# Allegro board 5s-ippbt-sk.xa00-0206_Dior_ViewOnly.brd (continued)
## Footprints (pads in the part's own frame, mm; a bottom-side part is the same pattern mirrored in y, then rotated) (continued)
MX_C0402_SMALL
  rect 0.457x0.508 smd: 1(0.419,0) 2(-0.419,0)
MX_C0402_SMALL_T01
  rect 0.457x0.508 smd: 1(0.419,0) 2(-0.419,0)
MX_C0603_SMALL
  rect 0.559x0.889 smd: 1(-0.67,0) 2(0.67,0)
MX_C0603_SMALL_T01
  rect 0.559x0.889 smd: 1(-0.67,0) 2(0.67,0)
MX_C0603_SMALL_T02
  rect 0.559x0.991 smd: 1(-0.67,0) 2(0.67,0)
MX_C0805_SMALL
  rect 0.813x1.397 smd: 1(0.9,0) 2(-0.9,0)
MX_C0805_SMALL_T02
  rect 0.711x1.397 smd: 1(-0.864,0) 2(0.864,0)
MX_C1206_H75
  rect 1.041x1.6 smd: 1(1.52,0) 2(-1.52,0)
MX_C3528
  rect 1.905x2.21 smd: 1(1.816,0) 2(-1.816,0)
MX_C7343D_H79
  rect 2.032x2.616 smd: 1(3.265,0) 2(-3.265,0)
MX_CESMD_260X260_H248
  rect 3.505x1.016 smd: 1(2.655,0) 2(-2.655,0)
MX_CHOKE_4P_79X47_FUKUI
  rect 0.889x0.356 smd: 1(-0.85,-0.425) 2(0.85,-0.425) 3(0.85,0.425) 4(-0.85,0.425)
MX_DC_PWR_JACK_6P_LF3
  oval 1.626x3.023 hole 0.61: 1(-1.12,7.65) 2_1(-3.9,5.3) 2_3(-3.9,0) 2_4(3.9,0)
  oval 1.372x2.769 hole 0.61: 2_2(3.9,5.3)
  oval 1.803x2.21 hole 0.787: 3(2.3,8)
MX_DDR3_DIMM_204P_24_4HD_AR
  round 1.6 hole 1.6 unplated: (-33.4,0)
  round 1.092 hole 1.092 unplated: (33.4,0)
  rect 0.356x2.007 smd: 1(-31.65,-4.1) 2(-31.35,4.1) 3(-31.05,-4.1) 4(-30.75,4.1) 5(-30.45,-4.1) 6(-30.15,4.1) 7(-29.85,-4.1) 8(-29.55,4.1) 9(-29.25,-4.1) 10(-28.95,4.1) 11(-28.65,-4.1) 12(-28.35,4.1) 13(-28.05,-4.1) 14(-27.75,4.1) 15(-27.45,-4.1) 16(-27.15,4.1) 17(-26.85,-4.1) 18(-26.55,4.1) 19(-26.25,-4.1) 20(-25.95,4.1) 21(-25.65,-4.1) 22(-25.35,4.1) 23(-25.05,-4.1) 24(-24.75,4.1) 25(-24.45,-4.1) 26(-24.15,4.1) 27(-23.85,-4.1) 28(-23.55,4.1) 29(-23.25,-4.1) 30(-22.95,4.1) 31(-22.65,-4.1) 32(-22.35,4.1) 33(-22.05,-4.1) 34(-21.75,4.1) 35(-21.45,-4.1) 36(-21.15,4.1) 37(-20.85,-4.1) 38(-20.55,4.1) 39(-20.25,-4.1) 40(-19.95,4.1) 41(-19.65,-4.1) 42(-19.35,4.1) 43(-19.05,-4.1) 44(-18.75,4.1) 45(-18.45,-4.1) 46(-18.15,4.1) 47(-17.85,-4.1) 48(-17.55,4.1) 49(-17.25,-4.1) 50(-16.95,4.1) 51(-16.65,-4.1) 52(-16.35,4.1) 53(-16.05,-4.1) 54(-15.75,4.1) 55(-15.45,-4.1) 56(-15.15,4.1) 57(-14.85,-4.1) 58(-14.55,4.1) 59(-14.25,-4.1) 60(-13.95,4.1) 61(-13.65,-4.1) 62(-13.35,4.1) 63(-13.05,-4.1) 64(-12.75,4.1) 65(-12.45,-4.1) 66(-12.15,4.1) 67(-11.85,-4.1) 68(-11.55,4.1) 69(-11.25,-4.1) 70(-10.95,4.1) 71(-10.65,-4.1) 72(-10.35,4.1) 73(-7.65,-4.1) 74(-7.35,4.1) 75(-7.05,-4.1) 76(-6.75,4.1) 77(-6.45,-4.1) 78(-6.15,4.1) 79(-5.85,-4.1) 80(-5.55,4.1) 81(-5.25,-4.1) 82(-4.95,4.1) 83(-4.65,-4.1) 84(-4.35,4.1) 85(-4.05,-4.1) 86(-3.75,4.1) 87(-3.45,-4.1) 88(-3.15,4.1) 89(-2.85,-4.1) 90(-2.55,4.1) 91(-2.25,-4.1) 92(-1.95,4.1) 93(-1.65,-4.1) 94(-1.35,4.1) 95(-1.05,-4.1) 96(-0.75,4.1) 97(-0.45,-4.1) 98(-0.15,4.1) 99(0.15,-4.1) 100(0.45,4.1) 101(0.75,-4.1) 102(1.05,4.1) 103(1.35,-4.1) 104(1.65,4.1) 105(1.95,-4.1) 106(2.25,4.1) 107(2.55,-4.1) 108(2.85,4.1) 109(3.15,-4.1) 110(3.45,4.1) 111(3.75,-4.1) 112(4.05,4.1) 113(4.35,-4.1) 114(4.65,4.1) 115(4.95,-4.1) 116(5.25,4.1) 117(5.55,-4.1) 118(5.85,4.1) 119(6.15,-4.1) 120(6.45,4.1) 121(6.75,-4.1) 122(7.05,4.1) 123(7.35,-4.1) 124(7.65,4.1) 125(7.95,-4.1) 126(8.25,4.1) 127(8.55,-4.1) 128(8.85,4.1) 129(9.15,-4.1) 130(9.45,4.1) 131(9.75,-4.1) 132(10.05,4.1) 133(10.35,-4.1) 134(10.65,4.1) 135(10.95,-4.1) 136(11.25,4.1) 137(11.55,-4.1) 138(11.85,4.1) 139(12.15,-4.1) 140(12.45,4.1) 141(12.75,-4.1) 142(13.05,4.1) 143(13.35,-4.1) 144(13.65,4.1) 145(13.95,-4.1) 146(14.25,4.1) 147(14.55,-4.1) 148(14.85,4.1) 149(15.15,-4.1) 150(15.45,4.1) 151(15.75,-4.1) 152(16.05,4.1) 153(16.35,-4.1) 154(16.65,4.1) 155(16.95,-4.1) 156(17.25,4.1) 157(17.55,-4.1) 158(17.85,4.1) 159(18.15,-4.1) 160(18.45,4.1) 161(18.75,-4.1) 162(19.05,4.1) 163(19.35,-4.1) 164(19.65,4.1) 165(19.95,-4.1) 166(20.25,4.1) 167(20.55,-4.1) 168(20.85,4.1) 169(21.15,-4.1) 170(21.45,4.1) 171(21.75,-4.1) 172(22.05,4.1) 173(22.35,-4.1) 174(22.65,4.1) 175(22.95,-4.1) 176(23.25,4.1) 177(23.55,-4.1) 178(23.85,4.1) 179(24.15,-4.1) 180(24.45,4.1) 181(24.75,-4.1) 182(25.05,4.1) 183(25.35,-4.1) 184(25.65,4.1) 185(25.95,-4.1) 186(26.25,4.1) 187(26.55,-4.1) 188(26.85,4.1) 189(27.15,-4.1) 190(27.45,4.1) 191(27.75,-4.1) 192(28.05,4.1) 193(28.35,-4.1) 194(28.65,4.1) 195(28.95,-4.1) 196(29.25,4.1) 197(29.55,-4.1) 198(29.85,4.1) 199(30.15,-4.1) 200(30.45,4.1) 201(30.75,-4.1) 202(31.05,4.1) 203(31.35,-4.1) 204(31.65,4.1)
  rect 4.699x6.807 smd: 207(-37.35,11.3) 208(37.35,11.3)
MX_DFN_6P_26_79X79_2PAD_IR
  rect 0.381x0.457 smd: 1(-0.65,-0.925) 2(0,-0.925) 3(0.65,-0.925) 4(0.65,0.925) 5(0,0.925) 6(-0.65,0.925)
  rect 1.041x0.965 smd: 7(-0.28,0.002)
  rect 0.229x0.787 smd: 8(0.735,0.002)
MX_DFN_10P_20_S118_P_RI_2V
  rect 0.279x0.61 smd: 1(-1,-1.35) 2(-0.5,-1.35) 3(0,-1.35) 4(0.5,-1.35) 5(1,-1.35) 6(1,1.35) 7(0.5,1.35) 8(0,1.35) 9(-0.5,1.35) 10(-1,1.35)
  rect 2.642x1.676 smd: 11(0,0)
  round 0.61 hole 0.305: 12(-1,0) 13(1,0)
MX_ESD_10P_20_98X39_NXP
  rect 0.295x0.483 smd: 1(-1,-0.363) 2(-0.5,-0.363) 3(0,-0.363) 4(0.5,-0.363) 5(1,-0.363) 6(1,0.363) 7(0.5,0.363) 8(0,0.363) 9(-0.5,0.363) 10(-1,0.363)
MX_FPC_10P_20_2H_RA_AC_H79
  rect 0.292x1.092 smd: 1(-2.25,1.95) 2(-1.75,1.95) 3(-1.25,1.95) 4(-0.75,1.95) 5(-0.25,1.95) 6(0.25,1.95) 7(0.75,1.95) 8(1.25,1.95) 9(1.75,1.95) 10(2.25,1.95)
  custom 0.6x0.6 smd: 11(-4.35,0) 12(4.35,0)
MX_FPC_12P_39_4HD
  rect 0.61x1.499 smd: 1(-2.75,-1.5) 2(-2.25,1.5) 3(-1.75,-1.5) 4(-1.25,1.5) 5(-0.75,-1.5) 6(-0.25,1.5) 7(0.25,-1.5) 8(0.75,1.5) 9(1.25,-1.5) 10(1.75,1.5) 11(2.25,-1.5) 12(2.75,1.5)
  rect 0.787x1.499 smd: 13(-3.75,-1.5) 14(-3.75,1.5) 15(3.75,-1.5) 16(3.75,1.5)
MX_HD_1X3P_100_LF3
  rect 1.575x1.575 hole 1.168: 1(-2.54,0)
  round 1.575 hole 1.168: 2(0,0) 3(2.54,0)
MX_HD_2X2P_50_JV
  rect 0.787x2.388 smd: 1(-0.635,-2.05) 2(-0.635,2.05) 3(0.635,-2.05) 4(0.635,2.05)
MX_HD_2X5P_79_K4_PINREX
  rect 0.838x2.591 smd: 1(-4,-2.05) 2(-4,2.05) 3(-2,-2.05) 5(0,-2.05) 6(0,2.05) 7(2,-2.05) 8(2,2.05) 9(4,-2.05) 10(4,2.05)
MX_HDMI_CON_19P_6H_SING_LF3
  round 1.702 hole 1.702 unplated: (-1.75,6.625)
  round 1.753 hole 1.753 unplated: (1.75,-6.625)
  round 0.94 hole 0.584: 1(0.75,-4.725) 2(-0.25,-4.147) 3(0.75,-3.57) 4(-0.25,-2.992) 5(0.75,-2.415) 6(-0.25,-1.837) 7(0.75,-1.26) 8(-0.25,-0.682) 9(0.75,-0.105) 10(-0.25,0.473) 11(0.75,1.05) 12(-0.25,1.628) 13(0.75,2.205) 14(-0.25,2.783) 15(0.75,3.36) 16(-0.25,3.938) 17(0.75,4.515) 18(-0.25,5.093) 19(0.75,5.67)
  oval 1.676x3.251 hole 0.66: 22(-3,-5.475) 23(-3,3.525) 24(3.5,-2.875) 25(3.5,6.625)
MX_HOLE_C59D59N
  round 1.499 hole 1.499 unplated: (0,0)
MX_HOLE_C118D118N
  round 2.997 hole 2.997 unplated: (0,0)
MX_HOLEC315D157N_M2P2V8
  round 3.988 hole 3.988 unplated: (0,0)
  round 0.61 hole 0.305: 2(0,3.004) 3(2.124,2.124) 4(3.004,0) 5(2.124,-2.124) 6(0,-3.004) 7(-2.124,-2.124) 8(-3.004,0) 9(-2.124,2.124)
MX_INDUCTOR_2P_287X260
  rect 2.845x2.997 smd: 1(-3.025,0) 2(3.025,0)
MX_L0603_SMALL
  rect 0.559x0.889 smd: 1(-0.67,0) 2(0.67,0)
MX_L0603_SMALL_T02
  rect 0.559x0.991 smd: 1(-0.67,0) 2(0.67,0)
MX_L0805_SMALL_T02_H43
  rect 0.711x1.397 smd: 1(-0.864,0) 2(0.864,0)
MX_MINI_PCI_67P_4HD_COLAY
  round 1.092 hole 1.092 unplated: (-10,0)
  round 1.6 hole 1.6 unplated: (10,0)
  rect 0.305x1.549 smd: 1(-9.25,5.275) 2(-9,-2.275) 3(-8.75,5.275) 4(-8.5,-2.275) 5(-8.25,5.275) 6(-8,-2.275) 7(-7.75,5.275) 16(-5.5,-2.275) 17(-5.25,5.275) 18(-5,-2.275) 19(-4.75,5.275) 20(-4.5,-2.275) 21(-4.25,5.275) 22(-4,-2.275) 23(-3.75,5.275) 24(-3.5,-2.275) 25(-3.25,5.275) 26(-3,-2.275) 27(-2.75,5.275) 28(-2.5,-2.275) 29(-2.25,5.275) 30(-2,-2.275) 31(-1.75,5.275) 32(-1.5,-2.275) 33(-1.25,5.275) 34(-1,-2.275) 35(-0.75,5.275) 36(-0.5,-2.275) 37(-0.25,5.275) 38(0,-2.275) 39(0.25,5.275) 40(0.5,-2.275) 41(0.75,5.275) 42(1,-2.275) 43(1.25,5.275) 44(1.5,-2.275) 45(1.75,5.275) 46(2,-2.275) 47(2.25,5.275) 48(2.5,-2.275) 49(2.75,5.275) 50(3,-2.275) 51(3.25,5.275) 52(3.5,-2.275) 53(3.75,5.275) 54(4,-2.275) 55(4.25,5.275) 56(4.5,-2.275) 57(4.75,5.275) 58(5,-2.275) 59(5.25,5.275) 60(5.5,-2.275) 61(5.75,5.275) 62(6,-2.275) 63(6.25,5.275) 64(6.5,-2.275) 65(6.75,5.275) 66(7,-2.275) 67(7.25,5.275) 68(7.5,-2.275) 69(7.75,5.275) 70(8,-2.275) 71(8.25,5.275) 72(8.5,-2.275) 73(8.75,5.275) 74(9,-2.275) 75(9.25,5.275)
  rect 1.194x2.743 smd: 76(-10.35,4.5) 77(10.35,4.5)
MX_MINI_PCI_67P_20_4HD_H165
  round 1.092 hole 1.092 unplated: (-10,0)
  round 1.6 hole 1.6 unplated: (10,0)
  rect 0.305x1.549 smd: 1(-9.25,5.275) 2(-9,-2.275) 3(-8.75,5.275) 4(-8.5,-2.275) 5(-8.25,5.275) 6(-8,-2.275) 7(-7.75,5.275) 8(-7.5,-2.275) 9(-7.25,5.275) 10(-7,-2.275) 11(-6.75,5.275) 20(-4.5,-2.275) 21(-4.25,5.275) 22(-4,-2.275) 23(-3.75,5.275) 24(-3.5,-2.275) 25(-3.25,5.275) 26(-3,-2.275) 27(-2.75,5.275) 28(-2.5,-2.275) 29(-2.25,5.275) 30(-2,-2.275) 31(-1.75,5.275) 32(-1.5,-2.275) 33(-1.25,5.275) 34(-1,-2.275) 35(-0.75,5.275) 36(-0.5,-2.275) 37(-0.25,5.275) 38(0,-2.275) 39(0.25,5.275) 40(0.5,-2.275) 41(0.75,5.275) 42(1,-2.275) 43(1.25,5.275) 44(1.5,-2.275) 45(1.75,5.275) 46(2,-2.275) 47(2.25,5.275) 48(2.5,-2.275) 49(2.75,5.275) 50(3,-2.275) 51(3.25,5.275) 52(3.5,-2.275) 53(3.75,5.275) 54(4,-2.275) 55(4.25,5.275) 56(4.5,-2.275) 57(4.75,5.275) 58(5,-2.275) 59(5.25,5.275) 60(5.5,-2.275) 61(5.75,5.275) 62(6,-2.275) 63(6.25,5.275) 64(6.5,-2.275) 65(6.75,5.275) 66(7,-2.275) 67(7.25,5.275) 68(7.5,-2.275) 69(7.75,5.275) 70(8,-2.275) 71(8.25,5.275) 72(8.5,-2.275) 73(8.75,5.275) 74(9,-2.275) 75(9.25,5.275)
  rect 1.194x2.743 smd: 76(-10.35,4.5) 77(10.35,4.5)
MX_NUT_CT256BD146_H71
  round 4.47 hole 3.708: 1(0,0)
MX_PHONE_JACK_6P_4HD_SG_LF5
  round 1.194 hole 1.194 unplated: (-3.5,0) (3,0)
  oval 1.88x1.219 hole 0.457: 1(0,7.3)
  oval 1.524x2.184 hole 0.508: 2(3.6,2.9)
  oval 1.473x2.134 hole 0.457: 3(-1.6,6) 4(-3.1,4) 5(-4.5,6) 8(-4.75,1.5)
  oval 2.134x1.473 hole 0.457: 6(0,0)
  oval 1.219x1.88 hole 0.457: 7(4.35,0.8)
MX_POLYSWITCH_2P_126X62_H28
  rect 1.499x2.057 smd: 1(-1.4,0) 2(1.4,0)
MX_POLYSWITCH_2P_0805_H30
  rect 0.991x1.499 smd: 1(-1.1,0) 2(1.1,0)
MX_QFN_20P_16_S118_PAD_4V
  rect 0.222x0.61 smd: 1(-0.8,-1.35) 2(-0.4,-1.35) 3(0,-1.35) 4(0.4,-1.35) 5(0.8,-1.35) 11(0.8,1.35) 12(0.4,1.35) 13(0,1.35) 14(-0.4,1.35) 15(-0.8,1.35)
  rect 0.61x0.222 smd: 6(1.35,-0.8) 7(1.35,-0.4) 8(1.35,0) 9(1.35,0.4) 10(1.35,0.8) 16(-1.35,0.8) 17(-1.35,0.4) 18(-1.35,0) 19(-1.35,-0.4) 20(-1.35,-0.8)
  rect 1.651x1.651 smd: 21(0,0)
  round 0.61 hole 0.305: 22(-0.521,0.521) 23(0.521,0.521) 24(-0.521,-0.521) 25(0.521,-0.521)
MX_QFN_24P_20_S157_PAD_T_4V
  rect 0.279x0.61 smd: 1(-1.25,-1.85) 2(-0.75,-1.85) 3(-0.25,-1.85) 4(0.25,-1.85) 5(0.75,-1.85) 6(1.25,-1.85) 13(1.25,1.85) 14(0.75,1.85) 15(0.25,1.85) 16(-0.25,1.85) 17(-0.75,1.85) 18(-1.25,1.85)
  rect 0.61x0.279 smd: 7(1.85,-1.25) 8(1.85,-0.75) 9(1.85,-0.25) 10(1.85,0.25) 11(1.85,0.75) 12(1.85,1.25) 19(-1.85,1.25) 20(-1.85,0.75) 21(-1.85,0.25) 22(-1.85,-0.25) 23(-1.85,-0.75) 24(-1.85,-1.25)
  rect 2.438x2.438 smd: 25(0,0)
  round 0.61 hole 0.305: 26(-0.914,0.914) 27(0.914,0.914) 28(-0.914,-0.914) 29(0.914,-0.914)
MX_QFN_28P_20_S197_P_GEN_4V
  rect 0.279x0.61 smd: 1(-1.5,-2.35) 2(-1,-2.35) 3(-0.5,-2.35) 4(0,-2.35) 5(0.5,-2.35) 6(1,-2.35) 7(1.5,-2.35) 15(1.5,2.35) 16(1,2.35) 17(0.5,2.35) 18(0,2.35) 19(-0.5,2.35) 20(-1,2.35) 21(-1.5,2.35)
  rect 0.61x0.279 smd: 8(2.35,-1.5) 9(2.35,-1) 10(2.35,-0.5) 11(2.35,0) 12(2.35,0.5) 13(2.35,1) 14(2.35,1.5) 22(-2.35,1.5) 23(-2.35,1) 24(-2.35,0.5) 25(-2.35,0) 26(-2.35,-0.5) 27(-2.35,-1) 28(-2.35,-1.5)
  rect 3.607x3.607 smd: 29(0,0)
  round 0.61 hole 0.305: 30(-1.499,1.499) 31(1.499,1.499) 32(-1.499,-1.499) 33(1.499,-1.499)
MX_QFN_32P_16_S157_P_H39_8V
  rect 0.222x0.508 smd: 1(-1.4,-1.901) 8(1.4,-1.901) 17(1.4,1.901) 24(-1.4,1.901)
  rect 0.222x0.61 smd: 2(-1,-1.85) 3(-0.6,-1.85) 4(-0.2,-1.85) 5(0.2,-1.85) 6(0.6,-1.85) 7(1,-1.85) 18(1,1.85) 19(0.6,1.85) 20(0.2,1.85) 21(-0.2,1.85) 22(-0.6,1.85) 23(-1,1.85)
  rect 0.508x0.222 smd: 9(1.901,-1.4) 16(1.901,1.4) 25(-1.901,1.4) 32(-1.901,-1.4)
  rect 0.61x0.222 smd: 10(1.85,-1) 11(1.85,-0.6) 12(1.85,-0.2) 13(1.85,0.2) 14(1.85,0.6) 15(1.85,1) 26(-1.85,1) 27(-1.85,0.6) 28(-1.85,0.2) 29(-1.85,-0.2) 30(-1.85,-0.6) 31(-1.85,-1)
  rect 2.667x2.667 smd: 33(0,0)
  round 0.61 hole 0.305: 34(-1.029,1.029) 35(-0.521,1.029) 36(0.521,1.029) 37(1.029,1.029) 38(-1.029,-1.029) 39(-0.521,-1.029) 40(0.521,-1.029) 41(1.029,-1.029)
MX_QFN_32P_16_S157_PAD_4V
  rect 0.222x0.508 smd: 1(-1.4,-1.901) 8(1.4,-1.901) 17(1.4,1.901) 24(-1.4,1.901)
  rect 0.222x0.61 smd: 2(-1,-1.85) 3(-0.6,-1.85) 4(-0.2,-1.85) 5(0.2,-1.85) 6(0.6,-1.85) 7(1,-1.85) 18(1,1.85) 19(0.6,1.85) 20(0.2,1.85) 21(-0.2,1.85) 22(-0.6,1.85) 23(-1,1.85)
  rect 0.508x0.222 smd: 9(1.901,-1.4) 16(1.901,1.4) 25(-1.901,1.4) 32(-1.901,-1.4)
  rect 0.61x0.222 smd: 10(1.85,-1) 11(1.85,-0.6) 12(1.85,-0.2) 13(1.85,0.2) 14(1.85,0.6) 15(1.85,1) 26(-1.85,1) 27(-1.85,0.6) 28(-1.85,0.2) 29(-1.85,-0.2) 30(-1.85,-0.6) 31(-1.85,-1)
  rect 2.667x2.667 smd: 33(0,0)
  round 0.61 hole 0.305: 34(-1.029,1.029) 35(1.029,1.029) 36(-1.029,-1.029) 37(1.029,-1.029)
MX_QFN_48P_16_S236_PAD_R_8V
  rect 0.222x0.61 smd: 1(-2.2,-2.85) 2(-1.8,-2.85) 3(-1.4,-2.85) 4(-1,-2.85) 5(-0.6,-2.85) 6(-0.2,-2.85) 7(0.2,-2.85) 8(0.6,-2.85) 9(1,-2.85) 10(1.4,-2.85) 11(1.8,-2.85) 12(2.2,-2.85) 25(2.2,2.85) 26(1.8,2.85) 27(1.4,2.85) 28(1,2.85) 29(0.6,2.85) 30(0.2,2.85) 31(-0.2,2.85) 32(-0.6,2.85) 33(-1,2.85) 34(-1.4,2.85) 35(-1.8,2.85) 36(-2.2,2.85)
  rect 0.61x0.222 smd: 13(2.85,-2.2) 14(2.85,-1.8) 15(2.85,-1.4) 16(2.85,-1) 17(2.85,-0.6) 18(2.85,-0.2) 19(2.85,0.2) 20(2.85,0.6) 21(2.85,1) 22(2.85,1.4) 23(2.85,1.8) 24(2.85,2.2) 37(-2.85,2.2) 38(-2.85,1.8) 39(-2.85,1.4) 40(-2.85,1) 41(-2.85,0.6) 42(-2.85,0.2) 43(-2.85,-0.2) 44(-2.85,-0.6) 45(-2.85,-1) 46(-2.85,-1.4) 47(-2.85,-1.8) 48(-2.85,-2.2)
  rect 4.648x4.648 smd: 49(0,0)
  round 0.61 hole 0.305: 50(-2.019,2.019) 51(-1.511,2.019) 52(1.511,2.019) 53(2.019,2.019) 54(-2.019,-2.019) 55(-1.511,-2.019) 56(1.511,-2.019) 57(2.019,-2.019)
MX_QFP_128P_16_630X630
  rect 0.191x1.499 smd: 1(-6.2,-7.86) 2(-5.8,-7.86) 3(-5.4,-7.86) 4(-5,-7.86) 5(-4.6,-7.86) 6(-4.2,-7.86) 7(-3.8,-7.86) 8(-3.4,-7.86) 9(-3,-7.86) 10(-2.6,-7.86) 11(-2.2,-7.86) 12(-1.8,-7.86) 13(-1.4,-7.86) 14(-1,-7.86) 15(-0.6,-7.86) 16(-0.2,-7.86) 17(0.2,-7.86) 18(0.6,-7.86) 19(1,-7.86) 20(1.4,-7.86) 21(1.8,-7.86) 22(2.2,-7.86) 23(2.6,-7.86) 24(3,-7.86) 25(3.4,-7.86) 26(3.8,-7.86) 27(4.2,-7.86) 28(4.6,-7.86) 29(5,-7.86) 30(5.4,-7.86) 31(5.8,-7.86) 32(6.2,-7.86) 65(6.2,7.86) 66(5.8,7.86) 67(5.4,7.86) 68(5,7.86) 69(4.6,7.86) 70(4.2,7.86) 71(3.8,7.86) 72(3.4,7.86) 73(3,7.86) 74(2.6,7.86) 75(2.2,7.86) 76(1.8,7.86) 77(1.4,7.86) 78(1,7.86) 79(0.6,7.86) 80(0.2,7.86) 81(-0.2,7.86) 82(-0.6,7.86) 83(-1,7.86) 84(-1.4,7.86) 85(-1.8,7.86) 86(-2.2,7.86) 87(-2.6,7.86) 88(-3,7.86) 89(-3.4,7.86) 90(-3.8,7.86) 91(-4.2,7.86) 92(-4.6,7.86) 93(-5,7.86) 94(-5.4,7.86) 95(-5.8,7.86) 96(-6.2,7.86)
  rect 1.499x0.191 smd: 33(7.86,-6.2) 34(7.86,-5.8) 35(7.86,-5.4) 36(7.86,-5) 37(7.86,-4.6) 38(7.86,-4.2) 39(7.86,-3.8) 40(7.86,-3.4) 41(7.86,-3) 42(7.86,-2.6) 43(7.86,-2.2) 44(7.86,-1.8) 45(7.86,-1.4) 46(7.86,-1) 47(7.86,-0.6) 48(7.86,-0.2) 49(7.86,0.2) 50(7.86,0.6) 51(7.86,1) 52(7.86,1.4) 53(7.86,1.8) 54(7.86,2.2) 55(7.86,2.6) 56(7.86,3) 57(7.86,3.4) 58(7.86,3.8) 59(7.86,4.2) 60(7.86,4.6) 61(7.86,5) 62(7.86,5.4) 63(7.86,5.8) 64(7.86,6.2) 97(-7.86,6.2) 98(-7.86,5.8) 99(-7.86,5.4) 100(-7.86,5) 101(-7.86,4.6) 102(-7.86,4.2) 103(-7.86,3.8) 104(-7.86,3.4) 105(-7.86,3) 106(-7.86,2.6) 107(-7.86,2.2) 108(-7.86,1.8) 109(-7.86,1.4) 110(-7.86,1) 111(-7.86,0.6) 112(-7.86,0.2) 113(-7.86,-0.2) 114(-7.86,-0.6) 115(-7.86,-1) 116(-7.86,-1.4) 117(-7.86,-1.8) 118(-7.86,-2.2) 119(-7.86,-2.6) 120(-7.86,-3) 121(-7.86,-3.4) 122(-7.86,-3.8) 123(-7.86,-4.2) 124(-7.86,-4.6) 125(-7.86,-5) 126(-7.86,-5.4) 127(-7.86,-5.8) 128(-7.86,-6.2)
MX_R0402_SHORT_SMALL
  rect 0.457x0.508 smd: 1(-0.419,0) 2(0.419,0)
MX_R0402_SMALL
  rect 0.457x0.508 smd: 1(-0.419,0) 2(0.419,0)
MX_R0402_SMALL_T01
  rect 0.457x0.508 smd: 1(-0.419,0) 2(0.419,0)
MX_R0603_SHORT_SMALL
  rect 0.559x0.889 smd: 1(-0.67,0) 2(0.67,0)
MX_R0603_SMALL_T01
  rect 0.559x0.889 smd: 1(-0.67,0) 2(0.67,0)
MX_R0805_SMALL_T02
  rect 0.711x1.397 smd: 1(-0.864,0) 2(0.864,0)
MX_R1206
  rect 1.041x1.6 smd: 1(-1.52,0) 2(1.52,0)
MX_R1206_H26
  rect 1.041x1.6 smd: 1(-1.52,0) 2(1.52,0)
MX_R1508
  rect 0.991x3.759 smd: 1(-1,0) 2(1,0)
MX_S0402_AMAZ
  rect 0.381x0.406 smd: 1(-0.35,0) 2(0.35,0)
MX_S0402_AMAZ_COLAY
  rect 0.635x0.635 smd: 1(-0.445,0) 2(0.445,0)
MX_SHORTPIN_RECTANGLE_LF3
  rect 0.737x0.813 smd: 1(-0.521,0) 2(0.521,0)
MX_SI7900EDN
  rect 0.305x0.914 smd: 1(-0.975,-1.608) 2(-0.325,-1.608) 3(0.325,-1.608) 4(0.975,-1.608)
  custom 0.603x0.603 smd: 5(-0.025,0.859)
MX_SMA
  rect 1.956x1.499 smd: 1(2.25,0) 2(-2.25,0)
MX_SMT_NUT_CT276B195D165
  round 7.01 hole 4.191: 1(0,0)
MX_SO8_H69
  rect 0.635x1.549 smd: 1(-1.91,-2.83) 2(-0.64,-2.83) 3(0.63,-2.83) 4(1.9,-2.83) 5(1.91,2.83) 6(0.64,2.83) 7(-0.63,2.83) 8(-1.9,2.83)
MX_SO_8FL_COLAY
  rect 0.762x1.524 smd: 1(-1.905,-2.848) 2(-0.635,-2.848) 3(0.635,-2.848) 4(1.905,-2.848)
  rect 4.547x4.826 smd: 5(0,1.083)
MX_SOD123
  rect 1.321x1.372 smd: 1(1.74,0) 2(-1.74,0)
MX_SOD323_H37
  rect 1.092x0.508 smd: 1(1.3,0) 2(-1.3,0)
MX_SOD523
  rect 0.635x0.508 smd: 1(0.82,0) 2(-0.82,0)
MX_SOD523_PHILIPS
  rect 0.635x0.508 smd: 1(-0.82,0) 2(0.82,0)
MX_SOIC_8P_26_122X193
  rect 0.356x1.448 smd: 1(-0.975,-2.335) 2(-0.325,-2.335) 3(0.325,-2.335) 4(0.975,-2.335) 5(0.975,2.335) 6(0.325,2.335) 7(-0.325,2.335) 8(-0.975,2.335)
MX_SOIC_8P_26_122X193_PA_TI
  rect 0.356x1.448 smd: 1(-0.975,-2.335) 2(-0.325,-2.335) 3(0.325,-2.335) 4(0.975,-2.335) 5(0.975,2.335) 6(0.325,2.335) 7(-0.325,2.335) 8(-0.975,2.335)
  rect 1.88x1.575 smd: 9(0,0)
MX_SOIC_8P_50_197X236
  rect 0.61x1.524 smd: 1(-1.905,-2.857) 2(-0.635,-2.857) 3(0.635,-2.857) 4(1.905,-2.857) 5(1.905,2.857) 6(0.635,2.857) 7(-0.635,2.857) 8(-1.905,2.857)
MX_SOIC_8P_50_197X236_PAD_R
  rect 0.635x1.549 smd: 1(-1.905,-2.833) 2(-0.635,-2.833) 3(0.635,-2.833) 4(1.905,-2.833) 5(1.905,2.833) 6(0.635,2.833) 7(-0.635,2.833) 8(-1.905,2.833)
  rect 3.607x2.692 smd: 9(0,0)
MX_SOIC_8P_50_213X311
  rect 0.635x1.88 smd: 1(-1.905,-3.62) 2(-0.635,-3.62) 3(0.635,-3.62) 4(1.905,-3.62) 5(1.905,3.62) 6(0.635,3.62) 7(-0.635,3.62) 8(-1.905,3.62)
MX_SOIC_28P_26_386X252_H43
  rect 0.356x1.499 smd: 1(-4.225,-3.06) 2(-3.575,-3.06) 3(-2.925,-3.06) 4(-2.275,-3.06) 5(-1.625,-3.06) 6(-0.975,-3.06) 7(-0.325,-3.06) 8(0.325,-3.06) 9(0.975,-3.06) 10(1.625,-3.06) 11(2.275,-3.06) 12(2.925,-3.06) 13(3.575,-3.06) 14(4.225,-3.06) 15(4.225,3.06) 16(3.575,3.06) 17(2.925,3.06) 18(2.275,3.06) 19(1.625,3.06) 20(0.975,3.06) 21(0.325,3.06) 22(-0.325,3.06) 23(-0.975,3.06) 24(-1.625,3.06) 25(-2.275,3.06) 26(-2.925,3.06) 27(-3.575,3.06) 28(-4.225,3.06)
MX_SOT23
  rect 1.27x0.686 smd: 1(1.041,-0.95) 2(1.041,0.95) 3(-1.041,0)
MX_SOT23_2D4_H44
  rect 0.711x1.016 smd: 1(-0.95,-1.301) 2(0.95,-1.301) 3(0,1.301)
MX_SOT23_2D4_H51
  rect 0.711x1.016 smd: 1(-0.95,-1.301) 2(0.95,-1.301) 3(0,1.301)
MX_SOT23_H43
  rect 1.27x0.686 smd: 1(1.041,-0.95) 2(1.041,0.95) 3(-1.041,0)
MX_SOT23_H43_COLAY
  rect 1.27x0.686 smd: 1(1.041,-0.95) 2(1.041,0.95) 3(-1.041,0)
MX_SOT23_H61
  rect 1.27x0.686 smd: 1(1.041,-0.95) 2(1.041,0.95) 3(-1.041,0)
MX_SOT23_S6
  rect 0.483x1.067 smd: 1(-0.95,-1.45) 2(0,-1.45) 3(0.95,-1.45) 4(0.95,1.45) 5(0,1.45) 6(-0.95,1.45)
MX_SOT23_TOREX_H57
  rect 1.524x0.711 smd: 1(1.248,-0.95) 2(1.248,0.95) 3(-1.248,0)
MX_SOT89
  rect 1.499x1.016 smd: 1(1.9,-1.5) 3(1.9,1.5)
  custom 0.55x0.55 smd: 2(0,0)
MX_SOT323
  rect 0.914x0.813 smd: 1(0.97,-0.65) 2(0.97,0.65) 3(-0.97,0)
MX_SOT323_S5
  rect 0.356x0.94 smd: 1(-0.65,-1.19) 2(0,-1.19) 3(0.65,-1.19) 4(0.65,1.19) 5(-0.65,1.19)
MX_SOT363
  rect 0.406x0.762 smd: 1(-0.65,-0.95) 2(0,-0.95) 3(0.65,-0.95) 4(0.65,0.95) 5(0,0.95) 6(-0.65,0.95)
MX_SOT363_PHILIPS
  rect 0.356x0.94 smd: 1(-0.65,-1.19) 2(0,-1.19) 3(0.65,-1.19) 4(0.65,1.19) 5(0,1.19) 6(-0.65,1.19)
MX_TP_SW_4P_4HOLD_DIPTRON
  round 1.016 hole 1.016 unplated: (-1.2,0) (1.2,0)
  oval 1.245x0.762 hole 0.356: 1(-1.1,-2.15) 2(1.1,-2.15)
  oval 1.168x1.676 hole 0.406: 5(-2.1,-3.55) 6(2.1,-3.55)
  oval 1.143x0.864 hole 0.457: L1(0,-3.05)
  round 1.041 hole 0.737: L2(0,0.2)
MX_TPC26B_S4_68
  round 0.66 smd: 1(0,0)
MX_TPC26T_S4_68
  round 0.66 smd: 1(0,0)
MX_USB_2X4P_4H_RA_VIT_LF5
  rect 1.321x1.321 hole 0.914: 1(-3.5,5.33)
  round 1.321 hole 0.914: 2(-1,5.33) 3(1,5.33) 4(3.5,5.33) 5(-3.5,2.71) 6(-1,2.71) 7(1,2.71) 8(3.5,2.71)
  oval 2.007x3.912 hole 0.991: 9(-6.4,5.68) 10(6.4,5.68) 11(-6.4,0) 12(6.4,0)
MX_WTOB_2P_49_2H_ACES
  rect 0.787x1.6 smd: 1(0.625,2.9) 2(-0.625,2.9)
  rect 2.108x2.997 smd: 3(3.175,0) 4(-3.175,0)
MX_WTOB_4P_49_2H_XINA
  rect 0.787x1.6 smd: 1(1.875,2.9) 2(0.625,2.9) 3(-0.625,2.9) 4(-1.875,2.9)
  rect 2.108x2.997 smd: 5(-4.425,0) 6(4.425,0)
MX_XTAL_2P_126X59_CITIZEN
  rect 1.092x1.905 smd: 1(-1.25,0) 2(1.25,0)
MX_XTAL_4P_126X98_HELE
  rect 1.397x1.194 smd: 1(-1.1,-0.85) 2(1.1,-0.85) 3(1.1,0.85) 4(-1.1,0.85)
MX_XTAL_4P_126X98_HOSON_H35
  rect 1.397x1.194 smd: 1(-1.1,-0.8) 2(1.1,-0.8) 3(1.1,0.8) 4(-1.1,0.8)
SD_CARD_9P_8HOLD_PLA_LF3
  round 1.194 hole 1.194 unplated: (-11.5,0)
  round 1.651 hole 1.651 unplated: (9.5,0)
  rect 1.397x2.794 smd: 11(11.5,1) 12(-13.7,1)
  oval 1.473x4.343 hole 0.457: 13(13.15,-8.85) 14(-13.15,-8.85)
  rect 0.711x1.499 smd: CD(-11.05,2.75) WP(-12.25,2.75)
  rect 0.991x1.499 smd: P1(6.88,2.75) P2(4.38,2.75) P3(1.88,2.75) P4(-0.62,2.75) P5(-3.12,2.75) P6(-5.62,2.75) P7(-8.05,2.75) P8(-9.75,2.75) P9(9.38,2.75)
SHORTPIN
  custom 0.184x0.184 smd: 1(-0.521,0) 2(0.521,0)
SMT_NUT_CT276B176D146_H220
  round 4.47 hole 3.708: 1(0,0)
T_DISPLAY_20P_26_6H_RA_LF3
  round 1.397 hole 1.397 unplated: (-1.6,7)
  round 1.448 hole 1.448 unplated: (1.6,-7)
  rect 1.016x1.016 hole 0.61: 1(0.75,-5.2)
  round 1.016 hole 0.61: 2(-0.75,-5.85) 3(0.75,-3.9) 4(-0.75,-4.55) 5(0.75,-2.6) 6(-0.75,-3.25) 7(0.75,-1.3) 8(-0.75,-1.95) 9(0.75,0) 10(-0.75,-0.65) 11(0.75,1.3) 12(-0.75,0.65) 13(0.75,2.6) 14(-0.75,1.95) 15(0.75,3.9) 16(-0.75,3.25) 17(0.75,5.2) 18(-0.75,4.55) 19(0.75,6.5) 20(-0.75,5.85)
  oval 0.914x2.87 hole 0.61: 23(2.58,-5.03)
  oval 1.676x2.743 hole 0.66: 24(2.58,6.77) 25(-2.58,-6.88)
  oval 1.016x2.972 hole 0.61: 26(-2.58,4.67)
TP_SW_4P_4HOLD_DIPTRON
  round 1.016 hole 1.016 unplated: (-1.2,0) (1.2,0)
  oval 1.245x0.762 hole 0.356: 1(-1.1,-2.15) 2(1.1,-2.15)
  oval 1.168x1.676 hole 0.406: 5(-2.1,-3.55) 6(2.1,-3.55)
  oval 1.143x0.864 hole 0.457: L1(0,-3.05)
  round 1.041 hole 0.737: L2(0,0.2)
TV_RTC_SHORT_6X20
  rect 0.152x0.508 smd: 1(-0.152,0) 2(0.152,0)
unnamed#2
  custom 0.286x0.286 smd: 1(0,0)
USB_1X4P_4HD_RA_JYEC_LF3
  rect 1.143x1.143 hole 0.737: 1(-3.5,5.6)
  round 1.143 hole 0.737: 2(-1,5.6) 3(1,5.6) 4(3.5,5.6)
  oval 1.803x2.311 hole 0.787: 5(-6.4,0) 6(6.4,0)
  oval 1.803x3.226 hole 0.787: 7(-6.4,6.1) 8(6.4,6.1)
USB_9P_4HOLD_RA_JYEC_LF5
  rect 1.118x1.118 hole 0.711: 1(-3.5,7.35)
  round 1.118 hole 0.711: 2(-1,7.35) 3(1,7.35) 4(3.5,7.35) 5(4,8.85) 6(2,8.85) 7(0,8.85) 8(-2,8.85) 9(-4,8.85)
  oval 1.803x2.718 hole 0.787: 10(-6.4,7.5) 11(6.4,7.5) 12(-6.4,0) 13(6.4,0)

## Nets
3V_EC_GPIO_MOS: ST7.1 U24.33
5V3V_VIN_C: PC18.1 PR27.2 PU3.12
5V_DUAL_DRI1: PC65.1 PR69.1 PR70.2
5VSB_EN: PC40.1 PR41.2 PR44.2 PR47.1 PU3.20
+3V_WLAN: J218.2 J218.4 J218.72 J218.74 WC4.1 WC5.1 WC6.1 WC15.1 WR34.1 WR59.1 WR81.2
+3VA: AR8.1 C272.1 O2R132.1 PC30.1 PR41.1 PU3.3 R191.1 R205.1 R209.1 R229.2 R3008.1 SD1.1 WR62.1
+3VA_EC: C260.1 C261.1 C262.1 C263.1 C264.1 D28.2 D32.1 D33.2 O2R1.1 R192.1 R205.2 R215.1 U24.26 U24.50 U24.92 U24.114 U24.121 U24.127
+3VA_SPI: R227.1 R228.1 R229.1 R230.1 U25.8
+3VS_CR: C257.1 OP1R2.1 PCB1.1 PJP1.2 U23.9
+3VSB_VIN: PC22.1 PC36.1 PC37.1 PL4.2 PQ6.1 PQ6.2 PQ6.5 PQ6.6 PQ6.7
+3VSUS: C151.1 C152.1 C153.1 C154.1 C307.1 C308.1 D2.2 D3.1 J8.12 LC17.1 LU1.11 LU1.23 LU1.32 Q27.3 R96.2
+5V: D1.1 FC2.1 FC3.1 FD5.3 MQ33.3 MR1.1 MR24.1 MR25.1 O2R246.1 P70.1 P110.8 P110.9 P110.10 PC62.1 PQ8.2 PR87.2 PR96.2 PR106.1 PR165.1 PR168.1 PR169.1 PR181.1 PR183.1 PR186.1 PR187.1 PR201.1 PR216.1 PR233.2 R176.1 R182.1 T1C3.1 T1C4.1 T1C17.1
+5V_AUX: PC9.1 PC15.1 PC16.1 PR15.1 PR16.1 PR17.1 PR18.1 PR19.1 PR20.1 PR23.1 PU1.3
+5V_DRI: PR68.1 PR72.2 PR75.1 PR79.1
+5V_DRI1: PC64.1 PR67.1 PR68.2
+5V_DUAL: CB6.1 PC63.1 PQ9.2 R18.2 R159.1 R160.1 R169.1 R170.1 U14.2 U14.3 U18.2 U18.3 UC5.1 UR3.1 UR7.1 UU3.27
+5V_HDMI: MQ33.2 MR2.1 VF1.2
+5V_PWRGD: O2R246.2 O2R248.1 U24.86
+5VA: PC26.1 PU3.13 SR65.1 SR71.1 SR625.1
+5VSB: D4.2 L1.1 PC29.1 PCE2.1 PJP4.1 PL5.2 PQ8.3 PQ9.3 PR35.1 PR51.1 PR60.1 PR111.1 PR126.1 PR137.1 PR146.1 PR170.1 PR172.1 U19.5 UU2.5
+5VSB_BST_C: PR28.1 PU3.17
+5VSB_BST_RC_C: PC24.2 PR28.2
+5VSB_FB_A: PC34.2 PR37.2 PR38.2 PU3.2
+5VSB_FBR_A: PC34.1 PC35.1 PJP4.2 PR37.1
+5VSB_HG_D: PC25.1 PQ4.3 PR30.2 PU3.16
+5VSB_LG_D: PC28.1 PQ5.3 PR33.2 PU3.15
+5VSB_PHASE_D: PC24.1 PC25.2 PC27.1 PL5.1 PQ4.4 PQ4.8 PQ5.1 PQ5.2 PQ5.5 PQ5.6 PQ5.7 PR30.1 PR32.1 PU3.18
+5VSB_SN_D: PC31.1 PR32.2
+5VSB_VIN: PC19.1 PC20.1 PC21.1 PL3.2 PQ4.1 PQ4.2 PQ4.5 PQ4.6 PQ4.7 PR27.1
+5VSB_VO1_A: PC33.1 PR35.2 PU3.14
+19V_DCIN: PC3.1 PJ1.1 PL1.2 PL2.2 PT1.1 PT2.1 PT3.1 PT4.1 PT5.1
+19VA: PC5.1 PJP3.1 PQ1.1 PQ1.2 PQ1.3 PR4.2 PR9.1 PR10.1 PR11.1
+19VA_IN: PC4.1 PC8.1 PJP2.1 PL1.1 PL2.1 PR4.1 PR5.1 PR6.1 PR7.1 PR8.1 PT6.1 PT7.1 PT8.1 PT9.1 PT10.1 PU1.1
+19VA_SN_A: PC7.1 PR5.2 PR6.2 PR7.2 PR8.2
+19VSB: PC23.1 PC93.1 PC109.1 PC134.1 PC154.1 PC194.1 PD1.2 PL3.1 PL4.1 PL7.1 PL8.1 PL10.1 PL11.1 PL13.1 PL14.1 PQ1.5 PQ10.3 PQ11.3 PQ15.3 PQ18.3 PQ21.3 PR74.1 PR76.1 PR85.1 PU7.8
+AV12: C252.1 C253.1 U23.7
+AVDD: DEC1.1 DEC2.1 DEC3.1 DEC5.1 DEC6.1 DEC7.1 DEC8.1 DEC9.1 HUBL1.1 R6.2 R10.2 R11.2 R13.2 R16.2 R17.2 R23.2 R24.2 R60310.2 UU3.5 UU3.9 UU3.14 UU3.28
+VCC_USB3: CB7.1 J11.1 J133.1 R149.2 U14.6 U14.7 U14.8 UC11.1 UCE1.1
+VCC_USB12: C941156.1 CE4118.1 CE4119.1 J17.1 J17.5 U18.6 U18.7 U18.8 UC3.1 UC4.1 UC10.1
AGND: AC3.2 AC4.2 AC5.2 AC6.2 AC42.2 AC48.2 AC49.2 AC50.2 AC52.2 AC56.2 AC57.2 AC58.2 AC59.2 AC60.2 AC61.2 AC62.2 AQ1.2 AQ2.2 AQ3.2 AR37.2 AR38.2 AU1.22 AU1.28 AU1.42 J27.5
DV12_S: C255.1 C256.1 U23.11
DV33_18: C254.1 U23.15
GND: AC7.2 AC38.2 AC39.2 AC40.2 AC41.2 AC43.2 AC44.2 AC45.2 AC46.2 AC50.1 AC52.1 AC53.2 AC54.2 AC55.2 AC63.1 AD1.2 AD2.2 AD3.2 AD4.2 AR37.1 AU1.49 AU1.50 AU1.51 AU1.52 AU1.53 AU1.54 AU1.55 AU1.56 AU1.57 C1.2 C2.2 C3.2 C4.2 C5.2 C10.2 C11.2 C12.2 C13.2 C14.2 C15.2 C16.2 C17.2 C18.2 C19.2 C20.2 C21.2 C22.2 C23.2 C24.2 C25.2 C26.2 C27.2 C28.2 C30.2 C31.2 C32.2 C33.2 C34.2 C35.2 C36.2 C37.2 C38.2 C39.2 C40.2 C41.2 C42.2 C43.2 C44.2 C45.2 C46.2 C47.2 C48.2 C49.2 C50.2 C51.2 C52.2 C53.2 C54.2 C55.2 C56.2 C57.2 C58.2 C59.2 C60.2 C61.2 C62.2 C63.2 C64.2 C65.2 C66.2 C67.2 C68.2 C69.2 C70.2 C71.2 C72.2 C73.2 C74.2 C75.2 C76.2 C77.2 C78.2 C79.2 C80.2 C81.2 C82.2 C83.2 C84.2 C85.2 C86.2 C89.2 C149.2 C150.2 C151.2 C152.2 C153.2 C154.2 C155.2 C156.2 C157.2 C158.2 C159.2 C160.2 C163.2 C240.2 C245.2 C246.2 C248.2 C249.2 C250.2 C251.2 C252.2 C253.2 C254.2 C255.2 C256.2 C257.2 C260.2 C261.2 C262.2 C263.2 C264.2 C267.2 C268.2 C269.2 C272.2 C302.1 C307.2 C308.2 C941134.2 C941135.2 C941136.2 C941137.2 C941138.2 C941139.2 C941140.2 C941141.2 C941156.2 C941162.2 C941163.2 CB1.2 CB2.2 CB3.2 CB6.2 CB7.2 CB10.2 CB12.2 CE4118.2 CE4119.2 CR6.5 CR6.6 D2.1 D3.2 D3C1.2 D3CB1.2 D3CB2.1 D3CB5.2 D3CB6.2 D3CB7.2 D3CB8.2 D3R3.2 D3R4.2 D4.1 D32.2 D33.1 DCB1.2 DCB3.2 DCB4.2 DCB5.2 DCB6.2 DCB7.2 DCB15.2 DCB16.2 DCB17.2 DCB18.2 DCB19.2 DCB20.2 DCB21.2 DCB22.2 DCB23.2 DCB24.2 DCB25.2 DEC1.2 DEC2.2 DEC3.2 DEC4.2 DEC5.2 DEC6.2 DEC7.2 DEC8.2 DEC9.2 E4.3 E69.3 E69.4 F3U1.4 FC1.2 FC2.2 FC3.2 H1.2 H1.3 H1.4 H1.5 H1.6 H1.7 H1.8 H1.9 H2.2 H2.3 H2.4 H2.5 H2.6 H2.7 H2.8 H2.9 H3.2 H3.3 H3.4 H3.5 H3.6 H3.7 H3.8 H3.9 H4.2 H4.3 H4.4 H4.5 H4.6 H4.7 H4.8 H4.9 H7.1 H8.1 H14.1 H20.1 H21.1 H22.1 H23.1 HC1.2 HC2.2 HC9.2 HC10.2 HC11.2 HC12.2 HC13.2 HC14.2 J8.15 J8.16 J11.4 J11.5 J11.6 J11.7 J11.8 J17.4 J17.8 J17.9 J17.10 J17.11 J17.12 J27.7 J27.8 J56.11 J56.12 J56.13 J56.14 J56.P3 J56.P6 J125.2 J125.5 J125.8 J125.11 J125.14 J125.16 J125.19 J125.23 J125.24 J125.25 J125.26 J133.4 J133.7 J133.10 J133.11 J133.12 J133.13 J134.27 J134.28 J134.29 J134.30 J137.2 J137.5 J137.8 J137.11 J137.17 J137.22 J137.23 J137.24 J137.25 J218.1 J218.7 J218.24 J218.33 J218.39 J218.45 J218.51 J218.57 J218.63 J218.69 J218.75 J218.76 J218.77 J219.1 J219.3 J219.21 J219.27 J219.33 J219.39 J219.45 J219.51 J219.57 J219.71 J219.73 J219.75 J219.76 J219.77 JP4.1 LANC1.2 LANC3.2 LANC4.2 LC1.2 LC2.2 LC16.2 LC17.2 LQ3.2 LR2.2 LU1.33 LU1.34 LU1.35 LU1.36 LU1.37 LU1.38 LU1.39 LU1.40 LU1.41 M1C9.2 M1C10.2 M1C14.2 M1R2.2 MCB1.2 MD1.2 MD2.2 MD3.2 MD5.2 MQ1.2 MQ3.2 MQ5.2 MQ6.2 MQ7.2 MQ8.2 MQ9.2 MQ22.2 MQ23.2 MQ25.2 MQ31.2 MQ32.2 MQ34.2 MQ36.2 MQ41.1 MQ41.4 MR26.1 O2C53.2 O2C56.2 O2C59.2 O2R248.2 O2R251.2 O2R252.2 OP1R3.1 P12.9 P12.11 P13.8 P70.3 P70.5 P70.6 P110.1 P110.4 P110.7 P110.11 P110.12 PC2.2 PC3.2 PC4.2 PC7.2 PC8.2 PC9.2 PC10.2 PC11.2 PC12.1 PC13.2 PC14.2 PC15.2 PC16.2 PC17.1 PC18.2 PC19.2 PC20.2 PC21.2 PC22.2 PC23.2 PC26.2 PC27.2 PC28.2 PC29.2 PC30.2 PC31.2 PC32.2 PC33.2 PC35.2 PC36.2 PC37.2 PC40.2 PC41.2 PC42.2 PC43.2 PC44.2 PC45.2 PC47.2 PC48.2 PC49.2 PC51.2 PC52.2 PC53.2 PC54.2 PC56.2 PC57.2 PC58.2 PC59.2 PC60.2 PC61.2 PC62.2 PC63.2 PC64.2 PC65.2 PC66.2 PC67.2 PC68.2 PC69.2 PC70.2 PC71.2 PC72.2 PC73.2 PC74.2 PC75.2 PC76.2 PC78.2 PC79.2 PC80.2 PC81.2 PC82.2 PC83.2 PC85.2 PC88.2 PC89.2 PC90.2 PC91.2 PC92.2 PC93.2 PC94.2 PC96.2 PC99.2 PC100.2 PC101.2 PC102.2 PC103.2 PC104.1 PC105.2 PC106.2 PC107.2 PC108.2 PC109.2 PC112.1 PC113.2 PC114.2 PC115.2 PC116.2 PC118.2 PC119.2 PC120.2 PC121.2 PC122.2 PC123.2 PC125.2 PC126.2 PC128.2 PC130.2 PC131.2 PC132.2 PC133.2 PC134.2 PC136.2 PC137.2 PC138.2 PC139.2 PC140.2 PC141.2 PC145.2 PC146.2 PC147.2 PC150.2 PC153.2 PC154.2 PC156.2 PC157.2 PC158.2 PC159.2 PC161.2 PC162.2 PC163.2 PC166.2 PC168.2 PC169.2 PC173.2 PC178.2 PC179.2 PC180.2 PC181.2 PC182.2 PC183.2 PC184.2 PC185.2 PC186.2 PC187.2 PC188.2 PC189.2 PC190.2 PC191.2 PC192.2 PC193.2 PC194.2 PCB1.2 PCE1.2 PCE2.2 PCE3.2 PCE4.2 PCE6.2 PCE7.2 PCE8.2 PCE9.2 PCE10.2 PD1.1 PJ1.2_1 PJ1.2_2 PJ1.2_3 PJ1.2_4 PJP12.2 PJP16.2 PQ3.2 PQ5.4 PQ5.8 PQ7.4 PQ7.8 PQ10.1 PQ11.1 PQ12.2 PQ13.2 PQ15.1 PQ16.2 PQ18.1 PQ19.2 PQ21.1 PQ22.2 PQ24.2 PQ25.2 PQ27.2 PQ28.2 PQ30.4 PQ30.8 PQ32.2 PQ33.2 PQ35.2 PQ36.2 PQ38.2 PQ41.2 PQ42.1 PQ42.2 PQ42.3 PQ43.2 PQ44.2 PQ46.1 PQ46.2 PQ46.3 PQ47.4 PQ47.8 PR3.2 PR22.2 PR24.2 PR25.2 PR26.1 PR33.1 PR36.2 PR38.1 PR39.2 PR48.2 PR50.1 PR56.2 PR65.2 PR78.2 PR79.2 PR88.2 PR97.2 PR105.2 PR115.2 PR121.2 PR122.1 PR127.2 PR133.1 PR138.2 PR144.2 PR156.2 PR159.2 PR160.2 PR177.2 PR178.2 PR189.2 PR190.2 PR199.2 PR209.2 PR224.1 PR226.2 PR230.2 PR244.2 PRT1.2 PRT2.1 PU1.2 PU2.11 PU2.12 PU2.13 PU3.21 PU3.22 PU3.23 PU3.24 PU3.25 PU4.8 PU4.9 PU5.8 PU5.9 PU6.8 PU6.9 PU7.4 PU8.1 PU8.3 PU8.11 PU8.14 PU8.21 PU8.22 PU8.23 PU8.24 PU8.25 PU9.33 PU9.34 PU9.35 PU9.36 PU9.37 Q1.2 Q2.2 Q9.2 Q30.2 Q31.2 Q32.2 Q33.2 Q38.2 Q39.2 Q41.2 Q9414.2 Q9415.2 Q9416.2 R19.1 R20.1 R21.1 R22.2 R91.2 R97.1 R149.1 R200.1 R225.2 R226.2 R233.2 R234.2 R60219.1 R60221.1 R60290.1 SC1.2 SC2.2 SC3.2 SC4.2 SC5.2 SC6.2 SC7.2 SC8.2 SC11.2 SC12.2 SC13.2 SC14.2 SC23.2 SC24.2 SC25.2 SC26.2 SC27.2 SC33.2 SC36.2 SC65.2 SC67.2 SR4.2 SR6.2 SR7.2 SR8.2 SR9.1 SR10.1 SR11.1 SR13.2 SR21.1 SR22.1 SR24.1 SR26.1 SR32.1 SR33.1 SR41.2 SR46.2 SR59.2 SR60.2 SR61.2 SR62.2 SR77.1 SR78.1 SR79.1 SR80.1 SR82.1 SR83.1 SR90.2 SR91.2 SR96.2 SR97.2 SR98.2 SR105.2 SR123.2 SR124.2 SR134.1 SR158.2 SR159.2 SR172.2 SR182.2 SR184.2 SR193.2 SR626.2 SR627.2 SSC3.2 SSC4.2 SSC5.2 SSC23.2 SW10.2 SW10.5 SW10.6 T1C3.2 T1C4.2 T1C17.2 TPC1.2 TPC2.2 TPC3.2 TPC4.2 TPR2.2 TPR5.2 TPU1.4 TPU1.11 TPU1.18 TPU1.25 U1.2 U3.4 U4.4 U14.1 U14.9 U18.1 U18.9 U19.2 U23.25 U23.26 U23.27 U23.28 U23.29 U24.1 U24.27 U24.49 U24.91 U24.113 U24.122 U25.4 UC3.2 UC4.2 UC5.2 UC6.2 UC7.2 UC8.2 UC9.2 UC10.2 UC11.2 UC12.2 UC13.2 UC14.2 UC15.2 UCE1.2 UU1.3 UU1.8 UU2.2 UU3.29 UU3.30 UU3.31 UU3.32 UU3.33 WC4.2 WC5.2 WC6.2 WC14.2 WC15.2 WQ6.1 WQ6.4 XBT1.1 XBT1.3 XBT1.4 XMM1.2 XMM1.3 XMM1.8 XMM1.9 XMM1.13 XMM1.14 XMM1.19 XMM1.20 XMM1.25 XMM1.26 XMM1.31 XMM1.32 XMM1.37 XMM1.38 XMM1.43 XMM1.44 XMM1.48 XMM1.49 XMM1.54 XMM1.55 XMM1.60 XMM1.61 XMM1.65 XMM1.66 XMM1.71 XMM1.72 XMM1.127 XMM1.128 XMM1.133 XMM1.134 XMM1.138 XMM1.139 XMM1.144 XMM1.145 XMM1.150 XMM1.151 XMM1.155 XMM1.156 XMM1.161 XMM1.162 XMM1.167 XMM1.168 XMM1.172 XMM1.173 XMM1.178 XMM1.179 XMM1.184 XMM1.185 XMM1.189 XMM1.190 XMM1.195 XMM1.196 XMM1.207 XMM1.208 XU1.A3 XU1.A5 XU1.A6 XU1.A11 XU1.A15 XU1.A19 XU1.A23 XU1.A27 XU1.A31 XU1.A35 XU1.A39 XU1.A43 XU1.A47 XU1.A49 XU1.A51 XU1.A52 XU1.AA1 XU1.AA3 XU1.AA16 XU1.AA19 XU1.AA21 XU1.AA32 XU1.AA35 XU1.AA38 XU1.AA53 XU1.AB4 XU1.AB6 XU1.AB10 XU1.AB41 XU1.AB45 XU1.AB47 XU1.AB48 XU1.AB50 XU1.AB51 XU1.AC16 XU1.AC18 XU1.AC19 XU1.AC21 XU1.AC25 XU1.AC33 XU1.AC35 XU1.AC36 XU1.AC38 XU1.AD7 XU1.AD16 XU1.AD18 XU1.AD19 XU1.AD21 XU1.AD25 XU1.AD32 XU1.AD33 XU1.AD47 XU1.AE1 XU1.AE3 XU1.AE4 XU1.AE6 XU1.AE8 XU1.AE9 XU1.AE11 XU1.AE12 XU1.AE14 XU1.AE40 XU1.AE42 XU1.AE43 XU1.AE45 XU1.AE46 XU1.AE48 XU1.AE50 XU1.AE51 XU1.AE53 XU1.AF10 XU1.AF12 XU1.AF25 XU1.AF32 XU1.AF47 XU1.AG16 XU1.AG25 XU1.AG36 XU1.AG38 XU1.AH4 XU1.AH6 XU1.AH7 XU1.AH9 XU1.AH41 XU1.AH45 XU1.AH47 XU1.AH48 XU1.AH50 XU1.AH51 XU1.AJ1 XU1.AJ3 XU1.AJ16 XU1.AJ21 XU1.AJ25 XU1.AJ27 XU1.AJ29 XU1.AJ30 XU1.AJ32 XU1.AJ33 XU1.AJ35 XU1.AJ38 XU1.AJ53 XU1.AK10 XU1.AK14 XU1.AK16 XU1.AK33 XU1.AK41 XU1.AK44 XU1.AM7 XU1.AM12 XU1.AM19 XU1.AM24 XU1.AM25 XU1.AM29 XU1.AM33 XU1.AM35 XU1.AM36 XU1.AM40 XU1.AM44 XU1.AM51 XU1.AN1 XU1.AN3 XU1.AN5 XU1.AN6 XU1.AN8 XU1.AN9 XU1.AN11 XU1.AN12 XU1.AN14 XU1.AN16 XU1.AN22 XU1.AN33 XU1.AN35 XU1.AN36 XU1.AN38 XU1.AN40 XU1.AN42 XU1.AN43 XU1.AN45 XU1.AN46 XU1.AN48 XU1.AN49 XU1.AN51 XU1.AN53 XU1.AP40 XU1.AT4 XU1.AT12 XU1.AT16 XU1.AT19 XU1.AT24 XU1.AT27 XU1.AT30 XU1.AT35 XU1.AT38 XU1.AT47 XU1.AT52 XU1.AU1 XU1.AU3 XU1.AU24 XU1.AU30 XU1.AU38 XU1.AU51 XU1.AV7 XU1.AV12 XU1.AV13 XU1.AV14 XU1.AV18 XU1.AV19 XU1.AV24 XU1.AV27 XU1.AV30 XU1.AV35 XU1.AV38 XU1.AV47 XU1.AV51 XU1.AW3 XU1.AW13 XU1.AW19 XU1.AW27 XU1.AW35 XU1.AY4 XU1.AY9 XU1.AY10 XU1.AY22 XU1.AY32 XU1.AY36 XU1.AY50 XU1.B2 XU1.B52 XU1.B53 XU1.BA14 XU1.BA19 XU1.BA22 XU1.BA27 XU1.BA32 XU1.BA35 XU1.BA40 XU1.BA53 XU1.BB19 XU1.BB27 XU1.BB35 XU1.BC1 XU1.BC2 XU1.BC20 XU1.BC22 XU1.BC26 XU1.BC28 XU1.BC32 XU1.BC34 XU1.BC42 XU1.BD19 XU1.BD24 XU1.BD27 XU1.BD30 XU1.BD35 XU1.BE1 XU1.BE2 XU1.BE8 XU1.BE19 XU1.BE35 XU1.BE53 XU1.BF4 XU1.BF12 XU1.BF16 XU1.BF24 XU1.BF30 XU1.BF36 XU1.BF38 XU1.BG1 XU1.BG31 XU1.BG34 XU1.BG39 XU1.BG42 XU1.BG45 XU1.BG49 XU1.BG53 XU1.BH1 XU1.BH2 XU1.BH52 XU1.BH53 XU1.BJ2 XU1.BJ3 XU1.BJ5 XU1.BJ7 XU1.BJ11 XU1.BJ15 XU1.BJ19 XU1.BJ23 XU1.BJ27 XU1.BJ31 XU1.BJ35 XU1.BJ39 XU1.BJ43 XU1.BJ47 XU1.BJ49 XU1.BJ51 XU1.BJ52 XU1.C1 XU1.C14 XU1.C31 XU1.C34 XU1.C39 XU1.C42 XU1.C45 XU1.C49 XU1.C53 XU1.D12 XU1.D16 XU1.D24 XU1.D30 XU1.D36 XU1.D38 XU1.E1 XU1.E8 XU1.E19 XU1.E35 XU1.E53 XU1.F2 XU1.F5 XU1.F7 XU1.F19 XU1.F24 XU1.F27 XU1.F30 XU1.F35 XU1.G10 XU1.G20 XU1.G22 XU1.G26 XU1.G28 XU1.G32 XU1.G34 XU1.G42 XU1.H19 XU1.H27 XU1.H35 XU1.J1 XU1.J16 XU1.J19 XU1.J22 XU1.J27 XU1.J32 XU1.J35 XU1.J40 XU1.J53 XU1.K4 XU1.K9 XU1.K14 XU1.K22 XU1.K32 XU1.K36 XU1.K50 XU1.L13 XU1.L19 XU1.L27 XU1.L35 XU1.M19 XU1.M26 XU1.M27 XU1.M28 XU1.M34 XU1.M35 XU1.M38 XU1.M47 XU1.M51 XU1.N1 XU1.N16 XU1.N38 XU1.N51 XU1.P4 XU1.P9 XU1.P13 XU1.P16 XU1.P19 XU1.P20 XU1.P24 XU1.P32 XU1.P35 XU1.P38 XU1.P47 XU1.P52 XU1.T40 XU1.U1 XU1.U3 XU1.U5 XU1.U6 XU1.U8 XU1.U9 XU1.U11 XU1.U12 XU1.U14 XU1.U16 XU1.U21 XU1.U30 XU1.U32 XU1.U40 XU1.U42 XU1.U43 XU1.U45 XU1.U46 XU1.U48 XU1.U49 XU1.U51 XU1.U53 XU1.V7 XU1.V12 XU1.V16 XU1.V19 XU1.V21 XU1.V35 XU1.V40 XU1.V44 XU1.V51 XU1.Y7 XU1.Y9 XU1.Y10 XU1.Y14 XU1.Y16 XU1.Y21 XU1.Y25 XU1.Y33 XU1.Y41 XU1.Y44 Y10.2 Y10.4 Y12.2 Y12.4 Y24.2 Y24.4
V1P0SX_PG: ST77.1 U24.17
VCCGT_SENSE: PR1.2 PR215.1 XU1.BB8
VCCGT_SENSE1: PJP11.2 PR217.1
VCCSENSE: PR2.2 PR234.1 XU1.P28
VCCSENSE1: PJP15.2 PR235.1
VSS_AH2: SR26.2 XU1.AH2
VSS_AH3: SR22.2 XU1.AH3
VSS_AM2: SR24.2 XU1.AM2
VSS_AM3: SR21.2 XU1.AM3
VSS_BB5: SR82.2 XU1.BB5
VSS_BB7: SR83.2 XU1.BB7
VSS_SENSE: PR3.1 PR221.2 PR241.1 XU1.N28
1P0VSB_PG_EC: ST49.1 U24.90
1P05V_ENQ: PQ33.1 PQ36.3 PR170.2
1P05V_ENR: PC126.1 PQ36.1 PR173.1
1P8V_ENQ: PQ35.1 PQ38.3 PR172.2
1P8V_ENR: PC128.1 PQ38.1 PR175.1
3PVO_EN: PC45.1 PR47.2 PU3.6
+1P0V: PC100.1 PC101.1 PC102.1 PC137.1 PJP7.2 PQ26.1 PQ26.2 PQ26.3 PR173.2 PR192.1 PR193.1 PR194.1 PR195.1 R9.1 SL1.2 SL2.2 SL3.2 SL5.2 SL7.2 SL8.2 SL9.2 SL10.2 SL11.2 SL15.1
+1P0V_EN_EC: PR141.1 U24.108
+1P0V_FB: PC97.2 PC98.2 PR134.1 PR142.1 PR144.1 PR145.1 PU7.6
+1P0V_FB_1: PC95.2 PR134.2
+1P0V_FB_2: PC97.1 PR135.1
+1P0V_FB_3: PC98.1 PR135.2 PR136.1 PR140.2
+1P0V_FB_4: PR140.1 PR142.2 PR143.1
+1P0V_FB_5: PC103.1 PR145.2
+1P0V_FB_6: PJP7.1 PR143.2
+1P0V_GATE: PC95.1 PQ26.4 PR136.2 PR138.1 PU7.7
+1P0V_PG: R60212.1 U24.109
+1P0V_REF: PC94.1 PQ27.3 PR132.1 PR133.2 PU7.5
+1P0V_REF_GATE: PC99.1 PQ27.1 PQ28.3 PR137.2
+1P0V_SX_EN_EC: ST61.1 U24.126
+1P0VSB: C22.1 C23.1 C24.1 C25.1 C26.1 PC60.1 PC61.1 PR63.1 PU5.6 SL16.1 XU1.B6 XU1.C3 XU1.C5 XU1.U22 XU1.V22 XU1.Y19
+1P0VSB_EN: PC59.1 PR61.1 PU5.2
+1P0VSB_FB: PC55.2 PR62.2 PR65.1 PU5.7
+1P0VSB_FB_R: PC55.1 PR62.1 PR63.2
+1P0VSB_PG: PC56.1 PR59.2 PU5.1
+1P0VSB_VDD: PC58.1 PR60.2 PU5.4
+1P05V: C27.1 C941136.1 PC82.1 PC83.1 PR113.1 PU6.6 SL12.2 XU1.AA33 XU1.AF33 XU1.AG33 XU1.AG35 XU1.U33 XU1.U35 XU1.V33
+1P5V: AC40.1 AC41.1 AU1.7 C75.1 PC89.1 PC90.1 PJP6.2 PQ23.4 PQ23.8 XU1.AM32
+1P05V_EN: PQ33.3 PR169.2 PR177.1 R60212.2
+1P5V_EN_EC: PR131.1 U24.106
+1P05V_EN_EC: PR247.1 U24.18
+1P5V_FB: PC86.2 PC87.2 PR117.1 PR124.1 PR127.1 PR129.1 PU7.2
+1P05V_FB: PC77.2 PR112.1 PR115.1 PU6.7
+1P5V_FB_1: PC84.2 PR117.2
+1P5V_FB_2: PC86.1 PR118.1
+1P5V_FB_3: PC87.1 PR118.2 PR119.1 PR123.2
+1P5V_FB_4: PR123.1 PR124.2 PR125.1
+1P5V_FB_5: PC91.1 PR129.2
+1P5V_FB_6: PJP6.1 PR125.2
+1P05V_FB_R: PC77.1 PR112.2 PR113.2
+1P5V_GATE_C: PC84.1 PQ23.3 PR119.2 PR121.1 PU7.1
+1P05V_PG: PC79.1 PR107.1 PR109.2 PU6.1
+1P05V_PG_1: PC76.1 PR104.1 PR106.2 PR107.2 PR108.2
+1P5V_REF: PC88.1 PQ24.3 PR120.1 PR122.2 PU7.3
+1P5V_REF_GATE: PC92.1 PQ24.1 PQ25.3 PR126.2
+1P05V_VDD: PC81.1 PR111.2 PU6.4
+1P8V: C71.1 C72.1 C73.1 C74.1 MR14.1 MR15.1 MR16.1 MR17.1 PC71.1 PQ17.2 R89.1 R60218.2 R60220.2 R60307.1 SC11.1 SC13.1 SR3.1 SR12.1 SR14.1 SR16.1 SR68.1 SR74.2 SR81.1 SR109.1 SR110.1 SR111.1 SR113.1 SR640.1 SR653.1 SR654.1 SR655.1 SR656.1 SR671.1 U3.1 U4.1 XU1.AM30 XU1.AN32 XU1.U38
+1P8V_DRI: PR92.2 PR93.2 PR94.1 PR97.1
+1P8V_DRI1: PC72.1 PR91.1 PR92.1
+1P8V_EN: PQ35.3 PR98.1 PR168.2 PR178.1 R60215.2
+1P8V_EN_2: PC73.1 PR95.1 PR96.1 PR98.2 PR99.2
+1P8V_EN_EC: PR99.1 U24.119
+1P8VSB: C28.1 F3R1.1 F3R2.1 F3R3.1 F3U1.8 FC1.1 P13.6 PC48.1 PC49.1 PQ17.3 PR54.1 PU4.6 Q3.2 Q3.5 SL6.1 SR34.1 SR36.1 SR37.1 SR47.2 SR55.1 SR56.2 SR57.2 SR58.2 SR94.1 SR95.1 SR156.2 SR157.2 SR167.2 SR170.2 SR171.2 SR183.2 SR185.2 SR196.1 SR641.1 SR642.1 SR664.1 SR665.1 UR1.1 XU1.N20 XU1.U25 XU1.V25
+1P8VSB_EN: PC51.1 PR52.1 PU4.2
+1P8VSB_EN_EC: ST50.1 U24.30
+1P8VSB_FB: PC50.2 PR53.2 PR56.1 PU4.7
+1P8VSB_FB_R: PC50.1 PR53.1 PR54.2
+1P8VSB_PG: PC54.1 PR57.2 PU4.1 R60291.2
+1P8VSB_PG_EC: R60291.1 U24.31
+1P8VSB_VDD: PC53.1 PR51.2 PU4.4
+1P35V: C48.1 C49.1 C50.1 C51.1 C52.1 C53.1 C54.1 C55.1 C941138.1 C941139.1 PC74.1 PQ20.2 PR175.2 SL13.2 SL14.2 XU1.AA25 XU1.AD36 XU1.AF19 XU1.AG19 XU1.AG32 XU1.U36 XU1.V36
+1P35V_DAUL_PG_G: HC9.1 Q38.1 Q39.3 R251.1
+1P35V_DRI: PR101.1 PR102.2 PR103.1 PR105.1
+1P35V_DRI1: PC75.1 PR100.1 PR101.2
+1P35V_DUAL: C10.1 C11.1 C12.1 C13.1 C31.1 C32.1 C33.1 C34.1 C35.1 C36.1 C941140.1 C941141.1 D3R1.1 D3R2.1 DCB7.1 DCB15.1 DCB16.1 DCB17.1 DCB18.1 DCB19.1 DCB20.1 DCB22.1 DCB23.1 DCB24.1 DCB25.1 PC80.1 PC96.1 PC113.1 PC119.1 PCE1.1 PCE4.1 PJP8.1 PL9.2 PQ20.3 PQ26.5 PU6.3 PU8.19 SR1.1 SR2.1 SR5.1 XMM1.75 XMM1.76 XMM1.81 XMM1.82 XMM1.87 XMM1.88 XMM1.93 XMM1.94 XMM1.99 XMM1.100 XMM1.105 XMM1.106 XMM1.111 XMM1.112 XMM1.117 XMM1.118 XMM1.123 XMM1.124 XU1.A48 XU1.AD38 XU1.AF38 XU1.AK38 XU1.AM38 XU1.AV41 XU1.AV42 XU1.BB46 XU1.BD49 XU1.BD52 XU1.BD53 XU1.BF44 XU1.BG51 XU1.BJ48 XU1.C51 XU1.D44 XU1.F49 XU1.F52 XU1.F53 XU1.H46 XU1.M41 XU1.M42 XU1.V38 XU1.Y38
+1P35V_DUAL_BOOT_C: PR147.1 PU8.18
+1P35V_DUAL_BST_C: PC110.2 PR147.2
+1P35V_DUAL_CS_A: PR160.1 PU8.13
+1P35V_DUAL_FB1_A: PC117.2 PR158.1 PR159.1 PU8.6
+1P35V_DUAL_FB_A: PC117.1 PC118.1 PJP8.2 PR158.2 PU8.5
+1P35V_DUAL_HG_D: PC111.1 PQ29.3 PR152.1 PU8.17
+1P35V_DUAL_LG_D: PC116.1 PQ30.3 PQ47.3 PR156.1 PU8.15
+1P35V_DUAL_PG: PR157.2 PU8.10 R213.2 R60208.1
+1P35V_DUAL_PHASE_D: PC110.1 PC111.2 PL9.1 PQ29.4 PQ29.8 PQ30.1 PQ30.2 PQ30.5 PQ30.6 PQ30.7 PQ47.1 PQ47.2 PQ47.5 PQ47.6 PQ47.7 PR152.2 PR153.1 PU8.16
+1P35V_DUAL_S3_A: PC112.2 PR149.2 PR151.2 PU8.7
+1P35V_DUAL_S5_A: PC114.1 PR154.2 PU8.8
+1P35V_DUAL_SN_C: PC115.1 PR153.2
+1P35V_DUAL_TON_A: PR148.2 PU8.9
+1P35V_DUAL_VDD: PC104.2 PR146.2 PU8.12
+1P35V_DUAL_VIN: PC105.1 PC106.1 PC107.1 PC108.1 PL7.2 PL8.2 PQ29.1 PQ29.2 PQ29.5 PQ29.6 PQ29.7 PR148.1
+1P35V_EN_EC: PR108.1 U24.35
+1P35V_PG: R60215.1 U24.20
+3P3V: AC38.1 AC39.1 AC53.1 AC54.1 AC55.1 AU1.11 C69.1 C267.1 CB1.1 D3CB6.1 D3CB7.1 D3CB8.1 FD3.3 FR1.1 FR5.1 J125.20 J219.2 J219.4 J219.70 J219.72 J219.74 L2.1 M1C14.1 M1R1.1 MQ36.1 O2R241.2 O2R243.2 O2R244.2 O2R247.1 P12.1 P12.3 PC68.1 PJP1.1 PQ14.4 PQ14.8 PR110.1 R93.2 R95.2 R60308.1 SC12.1 SC14.1 SL4.1 SR29.1 SR112.1 SR114.1 SR119.1 SR120.1 SR163.2 SSC3.1 SSC4.1 SSC5.1 SSC23.1 TPC1.1 TPC2.1 TPC3.1 TPC4.1 TPR1.1 TPU1.5 TPU1.10 TPU1.19 TPU1.24 U3.8 U4.8 U24.11 XMM1.199 XU1.AN27
+3P3V_DRI: PR82.2 PR83.2 PR84.1 PR88.1
+3P3V_DRI1: PC69.1 PR81.1 PR82.1
+3P3V_EN_1: PC70.1 PR85.2 PR86.1 PR87.1 PR90.2
+3P3V_EN_EC: PR90.1 U24.87
+3P3V_PG: O2C59.1 O2R247.2 U24.88
+3P3VSB: C67.1 C68.1 O2R245.1 PC1.1 PC43.1 PC52.1 PC57.1 PC85.1 PCE3.1 PJP5.1 PL6.2 PQ14.1 PQ14.2 PQ14.5 PQ14.6 PQ14.7 PQ23.1 PQ23.2 PQ23.5 PQ23.6 PQ23.7 PR34.1 PR57.1 PR59.1 PR109.1 PR120.2 PR132.2 PR157.1 PR182.1 PR196.1 PU4.3 PU5.3 Q27.2 R4.2 R8.1 R90.1 R251.2 R252.1 R357.1 R368.1 R60302.2 R60309.2 SR15.1 SR28.1 SR66.1 SR72.1 SR624.1 SR670.1 WR81.1 XU1.N18 XU1.N22 XU1.P18
+3P3VSB_BST_C: PR40.1 PU3.9
+3P3VSB_BST_RC_C: PC38.1 PR40.2
+3P3VSB_EN_EC: ST52.1 U24.34
+3P3VSB_FB_A: PC46.2 PR49.2 PR50.2 PU3.4
+3P3VSB_FBR: PC46.1 PC47.1 PJP5.2 PR49.1
+3P3VSB_HG_D: PC39.1 PQ6.3 PR43.1 PU3.10
+3P3VSB_LG_D: PC42.1 PQ7.3 PR48.1 PU3.11
+3P3VSB_PG: O2C56.1 O2R245.2 U24.48
+3P3VSB_PHASE_D: PC38.2 PC39.2 PC41.1 PL6.1 PQ6.4 PQ6.8 PQ7.1 PQ7.2 PQ7.5 PQ7.6 PQ7.7 PR43.2 PR46.1 PU3.8
+3P3VSB_SN_D: PC44.1 PR46.2
+BATT: R188.1 R60214.1 SC2.1 SD1.3 U24.3 XU1.P22
+RTCBAT: SR154.1 XBT1.2
+RTCBAT_R: SD1.2 SR154.2
+V_AXG_BOOT: PR166.1 PU9.26
+V_AXG_BOOT1: PC124.1 PR166.2
+V_AXG_COMP: PC149.1 PC152.1 PR209.1 PU9.28
+V_AXG_COMP1: PC152.2 PR214.1
+V_AXG_FB: PC149.2 PR208.1 PR211.2 PR213.2 PR214.2 PU9.29
+V_AXG_FB1: PC148.2 PR211.1
+V_AXG_FB2: PC146.1 PR208.2
+V_AXG_FB3: PC147.1 PC148.1 PR213.1 PR215.2 PR217.2
+V_AXG_HG_D: PC135.1 PQ31.4 PR188.1 PU9.25
+V_AXG_ISUMN: PC151.2 PR210.2 PR216.2 PU9.31
+V_AXG_ISUMN1: PC151.1 PR212.2
+V_AXG_ISUMN2: PC142.2 PC143.2 PC144.2 PC150.1 PJP10.2 PR205.2 PR206.2 PR210.1 PR212.1
+V_AXG_ISUMP: PC142.1 PC143.1 PC144.1 PR203.2 PR205.1 PR207.1 PU9.32
+V_AXG_ISUMP1: PJP9.2 PR203.1
+V_AXG_LGATE_D: PC140.1 PQ42.4 PR199.1 PU9.23
+V_AXG_NTC: PR222.1 PU9.1
+V_AXG_NTC1: PR222.2 PR224.2 PRT1.1
+V_AXG_PHASE: PC124.2 PC135.2 PC138.1 PJP9.1 PL12.1 PQ31.1 PQ31.2 PQ31.3 PQ42.5 PR188.2 PR191.1 PU9.24
+V_AXG_RTC: PC153.1 PR219.1 PR221.1 PU9.30
+V_AXG_RTC_R: PJP12.1 PR219.2
+V_AXG_SN: PC139.1 PR191.2
+VAXG_ISUMP2: PR206.1 PR207.2
+VCORE: C79.1 C80.1 C81.1 C82.1 C83.1 C84.1 C85.1 C86.1 PC178.1 PC179.1 PC180.1 PC181.1 PC182.1 PC183.1 PC184.1 PC185.1 PCE6.1 PCE7.1 PCE8.1 PJP14.1 PJP15.1 PL15.2 PR2.1 XU1.AA27 XU1.AA29 XU1.AA30 XU1.AC27 XU1.AC29 XU1.AC30 XU1.AD27 XU1.AD29 XU1.AD30 XU1.AF27 XU1.AF29 XU1.AG27 XU1.AG29 XU1.AG30 XU1.P26 XU1.P27 XU1.U27 XU1.U29 XU1.V27 XU1.V29 XU1.V30 XU1.Y27 XU1.Y29 XU1.Y30
+VCORE&+V_AXG_VR_ON: PC145.1 PD2.1 PD2.2 PR204.2 PU9.2
+VCORE_+19V: PC156.1 PC157.1 PC158.1 PC159.1 PL13.2 PL14.2 PQ45.5
+VCORE_BOOT: PR218.1 PU9.16
+VCORE_BOOT1: PC155.1 PR218.2
+VCORE_COMP: PC165.1 PC167.1 PR226.1 PU9.14
+VCORE_COMP1: PC167.2 PR232.1
+VCORE_FB: PC165.2 PR225.1 PR229.2 PR231.2 PR232.2 PU9.13
+VCORE_FB1: PC164.2 PR229.1
+VCORE_FB2: PC161.1 PR225.2
+VCORE_FB3: PC163.1 PC164.1 PR231.1 PR234.2 PR235.2
+VCORE_HG_D: PC160.1 PQ45.4 PR223.1 PU9.17
+VCORE_ISUMN: PC174.2 PR243.2 PU9.11
+VCORE_ISUMN1: PC174.1 PR245.2
+VCORE_ISUMN2: PC170.2 PC171.2 PC172.2 PC173.1 PJP14.2 PR238.2 PR239.2 PR243.1 PR245.1
+VCORE_ISUMP: PC170.1 PC171.1 PC172.1 PR236.2 PR238.1 PR240.1 PU9.10
+VCORE_ISUMP1: PJP13.2 PR236.1
+VCORE_ISUMP2: PR239.1 PR240.2
+VCORE_LGATE_D: PC166.1 PQ46.4 PR230.1 PU9.19
+VCORE_NTC: PR242.2 PU9.7
+VCORE_NTC1: PR242.1 PR244.1 PRT2.2
+VCORE_PHASE: PC155.2 PC160.2 PC162.1 PJP13.1 PL15.1 PQ45.1 PQ45.2 PQ45.3 PQ46.5 PR223.2 PR228.1 PU9.18
+VCORE_RTN: PC169.1 PR237.1 PR241.2 PU9.12
+VCORE_RTN_R: PJP16.1 PR237.2
+VCORE_SN: PC168.1 PR228.2
+VNN: C56.1 C57.1 C58.1 C59.1 C60.1 C61.1 C76.1 C77.1 C78.1 PC186.1 PC187.1 PC188.1 PC189.1 PC190.1 PC191.1 PC192.1 PC193.1 PCE9.1 PCE10.1 PJP10.1 PJP11.1 PL12.2 PR1.1 XU1.AA24 XU1.AC22 XU1.AC24 XU1.AD22 XU1.AD24 XU1.AF22 XU1.AF24 XU1.AG22 XU1.AG24 XU1.AJ22 XU1.AJ24 XU1.AK22 XU1.AK24 XU1.AK25 XU1.AK27 XU1.AK29 XU1.AK30 XU1.AK32 XU1.AM22
+VNN_+19V: PC130.1 PC131.1 PC132.1 PC133.1 PL10.2 PL11.2 PQ31.5
+VTT_DDR: DCB1.1 DCB3.1 DCB4.1 DCB5.1 DCB6.1 DCB21.1 O2R240.1 PC120.1 PC121.1 PR164.1 PU8.20 XMM1.203 XMM1.204
+VTT_DDR_VTTSNS_A: PR164.2 PU8.2
+VTT_EN_EC: PR149.1 U24.89
+VTT_PG: O2C54.1 O2R240.2 U24.68
+VTTREF_A: PC122.1 PU8.4
AD_CSN: PC11.1 PR13.1 PU2.10
AD_CSP: PC10.1 PR12.1 PU2.1
ADATPTER_ID: O2R1.2 PJ1.3 U24.28
AZ_BITCLK: AC45.1 AU1.5 SR87.1
AZ_BITCLK_S: SR87.2 XU1.BJ21
AZ_RST#: AC44.1 AR10.1 AU1.6 SR86.1
AZ_RST#_S: SR86.2 XU1.BG22
AZ_SDATA_IN0: AC43.1 AR1.1 SR88.1
AZ_SDATA_IN0_S: SR88.2 XU1.BG19
AZ_SDATA_OUT: D1.3 R5.1 SR89.1
AZ_SDATA_OUT_S: SR89.2 XU1.BG20
AZ_SYNC: AU1.9 SR85.1
AZ_SYNC_S: SR85.2 XU1.BH20
BOARD_ID_0: SR56.1 SR61.1 XU1.B18
BOARD_ID_1: SR57.1 SR60.1 XU1.B16
BOARD_ID_2: SR58.1 SR59.1 XU1.C18
BT_ON/OFF#: U24.104 WR64.1
BT_ON/OFF#_G: WQ6.2 WQ6.3 WR62.2
BT_ON/OFF#_Q: J218.54 WQ6.6 WR59.2
BT_ON/OFF#_R: WQ6.5 WR64.2
BT_USBN2: J218.5 XU1.J12
BT_USBP2: J218.3 XU1.K12
CA_DET: MQ41.5 MQ41.6 MQ42.2 MQ42.5 MR25.2
CAD_PIN13: J125.13 MQ41.2 MR26.2
CARD_3V3: F3.1 R198.1 U23.10
CARD_3V3_F: C245.1 C246.1 C249.1 F3.2 J56.P4 R198.2
CBN: AC51.2 AU1.21
CBP: AC51.1 AU1.24
CK_100M_CR: C250.1 U23.3 XU1.AM6
CK_100M_CR#: C251.1 U23.4 XU1.AM4
CLK_PCIE_LAN: LU1.15 XU1.AK6
CLK_PCIE_LAN#: LU1.16 XU1.AK4
CLK_PCIE_WLAN: J218.49 XU1.AF7
CLK_PCIE_WLAN#: J218.47 XU1.AF9
CLK_REQ1_WLAN#: J218.53 SR654.2 XU1.BD7
CLKRUN#_R: SR108.1 XU1.BG16
CLR_CMOS: C150.1 E69.2 SR672.1 SR673.1 SR674.1
CLRCMOS_GPIO: SR182.1 SR672.2 XU1.J3
CORE_V1P0_S3: SL12.1 XU1.AC32 XU1.Y32
CPU_BKLTEN: ST19.1 XU1.C27
CPU_PWM_18: ST3.1 XU1.B26
CPU_VDDEN: ST18.1 XU1.B28
CPU_VRON: PR204.1 U24.84
CPUFAN_PWM: FR1.2 FR3.1 U24.32
CPUFAN_TACH: FD4.1 FD4.2 FR4.2 FR5.2 U24.47
CPVEE: AC62.1 AU1.20
CR6_R: CR6.L1 R176.2
CR_PE1_RXN2: SC22.2 XU1.AP10
CR_PE1_RXN2_C: SC22.1 U23.6
CR_PE1_RXP2: SC21.2 XU1.AP12
CR_PE1_RXP2_C: SC21.1 U23.5
CR_PE1_TXN2: SC9.1 U23.2
CR_PE1_TXP2: SC10.1 U23.1
DDI0_RCOMP_N: SR18.1 XU1.AK13
DDI0_RCOMP_P: SR18.2 XU1.AK12
DDI1_AUXN: ST2.1 XU1.AK2
DDI1_AUXP: ST1.1 XU1.AK3
DDI_V1P0_S0IX: C20.1 C21.1 C941134.1 C941135.1 SL3.1 XU1.AJ18 XU1.AK19 XU1.AK21 XU1.AM16
DDR3_DRAMRST0#: D3C1.1 HC1.1 XMM1.30 XU1.P41
DDR_THERMAL_EC: O2R241.1 PRT3.1 U24.71
DDRTEMP_HOT_EC_R: ST82.1 U24.123
DEPOP#: AC7.1 AQ3.1 AR10.2
DIMM_CA_VREF_A: C89.1 D3CB1.1 D3CB5.1 D3R2.2 D3R4.1 XMM1.126
DIMM_VREF_A: D3CB2.2 D3R1.2 D3R3.1 XMM1.1
DP_AUXN: M1C21.1 XU1.AL1
DP_AUXN_C: M1C21.2 MQ42.4
DP_AUXN_LS: J125.17 M1R1.2 MQ40.3 MQ42.3
DP_AUXP: M1C20.1 XU1.AL3
DP_AUXP_C: M1C20.2 MQ42.1
DP_AUXP_LS: J125.15 M1R2.1 MQ40.1 MQ42.6
DP_DDPC_CTRL: MQ40.2 MQ40.5 MQ41.3 MR24.2
DP_HPD#: MQ3.3 SR12.2 XU1.D27
DP_HPDET: J125.18 MD5.1 MQ3.1 SR13.1
DP_TMDS_DATA0_N: J125.3 M1C13.2
DP_TMDS_DATA0_P: J125.1 M1C11.2
DP_TMDS_DATA1_N: J125.6 M1C15.2
DP_TMDS_DATA1_P: J125.4 M1C12.2
DP_TMDS_DATA2_N: J125.9 M1C17.2
DP_TMDS_DATA2_P: J125.7 M1C16.2
DP_TMDS_DATA3_N: J125.12 M1C19.2
DP_TMDS_DATA3_P: J125.10 M1C18.2
DP_TXN0: M1C13.1 XU1.AV2
DP_TXN1: M1C15.1 XU1.AT3
DP_TXN2: M1C17.1 XU1.AR1
DP_TXN3: M1C19.1 XU1.AP2
DP_TXP0: M1C11.1 XU1.AV3
DP_TXP1: M1C12.1 XU1.AT2
DP_TXP2: M1C16.1 XU1.AR3
DP_TXP3: M1C18.1 XU1.AP3
DPPP_DDC_CLK: MQ40.6 SR16.2 XU1.C28
DPPP_DDC_DATA: MQ40.4 SR14.2 XU1.C26
DRAM_CORE_PWORK_EC: SC26.1 SR153.2 SR663.1
DRAM_CORE_PWORK_EC_C: SR153.1 U24.16
DRAM_CORE_PWROK: HC10.1 Q9415.3 SR1.2 XU1.AB42
DRAM_RCOMP0: SR9.2 XU1.AD44
DRAM_RCOMP1: SR10.2 XU1.AF45
DRAM_RCOMP2: SR11.2 XU1.AD45
DRAM_S4_PWROK_EC: R60209.1 U24.80
DRAM_V1P0_S0IX: C16.1 C17.1 C18.1 C19.1 SL5.1 XU1.AA36 XU1.AD35 XU1.AF35 XU1.AF36 XU1.AJ36 XU1.AK35 XU1.AK36 XU1.Y35 XU1.Y36
DRAM_VDD_S4_PWROK: Q38.3 SR2.2 XU1.AD42
DRAM_VREF_CPU: HC2.1 R1.2 XU1.AF44
DRAM_VREF_CPU_R: R1.1 SR5.2 SR6.1
EC_AGND: C265.2 C266.2 JP4.2 O2C54.2 PRT3.2 PRT4.2 PRT5.2 U24.75
EC_AVCC: C265.1 C266.1 R209.2 U24.74
EC_GPF0: ST83.1 U24.85
EC_RST#: D28.1 D29.1 PC2.1 R192.2 SC25.1 U24.14
EC_RST#_D: D29.2 R191.2
EC_SPI_WP#: R228.2 U25.3
EC_VCORE: C268.1 C269.1 R226.1 U24.12
EC_XIN: R225.1 U24.128
EC_XOUT: ST84.1 U24.2
ENTRIP1: PR36.1 PU3.1
ENTRIP2: PR39.1 PU3.5
EXT_SCI#: R60293.1 R60306.1
EXT_SCI#_1P8V: MQ31.3 SR671.2 XU1.B14
EXT_SCI#_D: R60293.2 U24.23
FAN_PWM_R: FD3.1 FR3.2 P70.2
FDO_EN#: E4.2 Q7.3 R7.2 XU1.BC30
FDO_EN#_P: E4.1 R89.2
GPIO_RCOMP: SR62.1 XU1.N26
GPIO_S0_NC13: R60290.2 ST5.1 XU1.A29
GPIO_S0_NC14: ST6.1 XU1.C29
GPIO_S0_SC[56]: R60218.1 R60219.2 XU1.BC12
GPIO_S0_SC[58]: ST80.1 XU1.BC14
GPIO_S0_SC[063]: R60220.1 R60221.2 XU1.BA30
GPIO_S5[03]: SR55.2 XU1.A17
GPIO_S5[34]: SR47.1 SR49.2 XU1.K2
GPIO_S5[35]: SR167.1 ST20.1 XU1.K3
GPIO_S5[36]: SR170.1 ST81.1 XU1.M2
GPIO_S5[37]: SR171.1 ST30.1 XU1.N3
GPIO_S5[41]: SR183.1 ST22.1 XU1.P3
GPIO_S5[42]: SR184.1 ST23.1 XU1.H3
GPIO_S5[43]: SR185.1 ST24.1 XU1.B12
GPIO_V1P0_S3: C47.1 SL10.1 XU1.AN25
HD_LED#: R184.1 SR74.1 XU1.AY12
HDA_LPE_RCOMP: SR90.1 XU1.BF20
HDMI_CLKN: M1C8.1 XU1.AC1
HDMI_CLKP: M1C7.1 XU1.AC3
HDMI_DDC_CLK_LS: J137.15 M1C10.1 MD3.1 MQ37.3 MR19.2
HDMI_DDC_DATA_LS: J137.16 M1C9.1 MD2.1 MQ37.6 MR18.2
HDMI_DDC_SCL: MQ37.4 MR14.2 XU1.G30
HDMI_DDC_SDA: MQ37.1 MR15.2 XU1.P30
HDMI_HPD#: MQ1.3 SR3.2 XU1.K30
HDMI_HPDET: J137.19 MD1.1 MQ1.1 SR4.1
